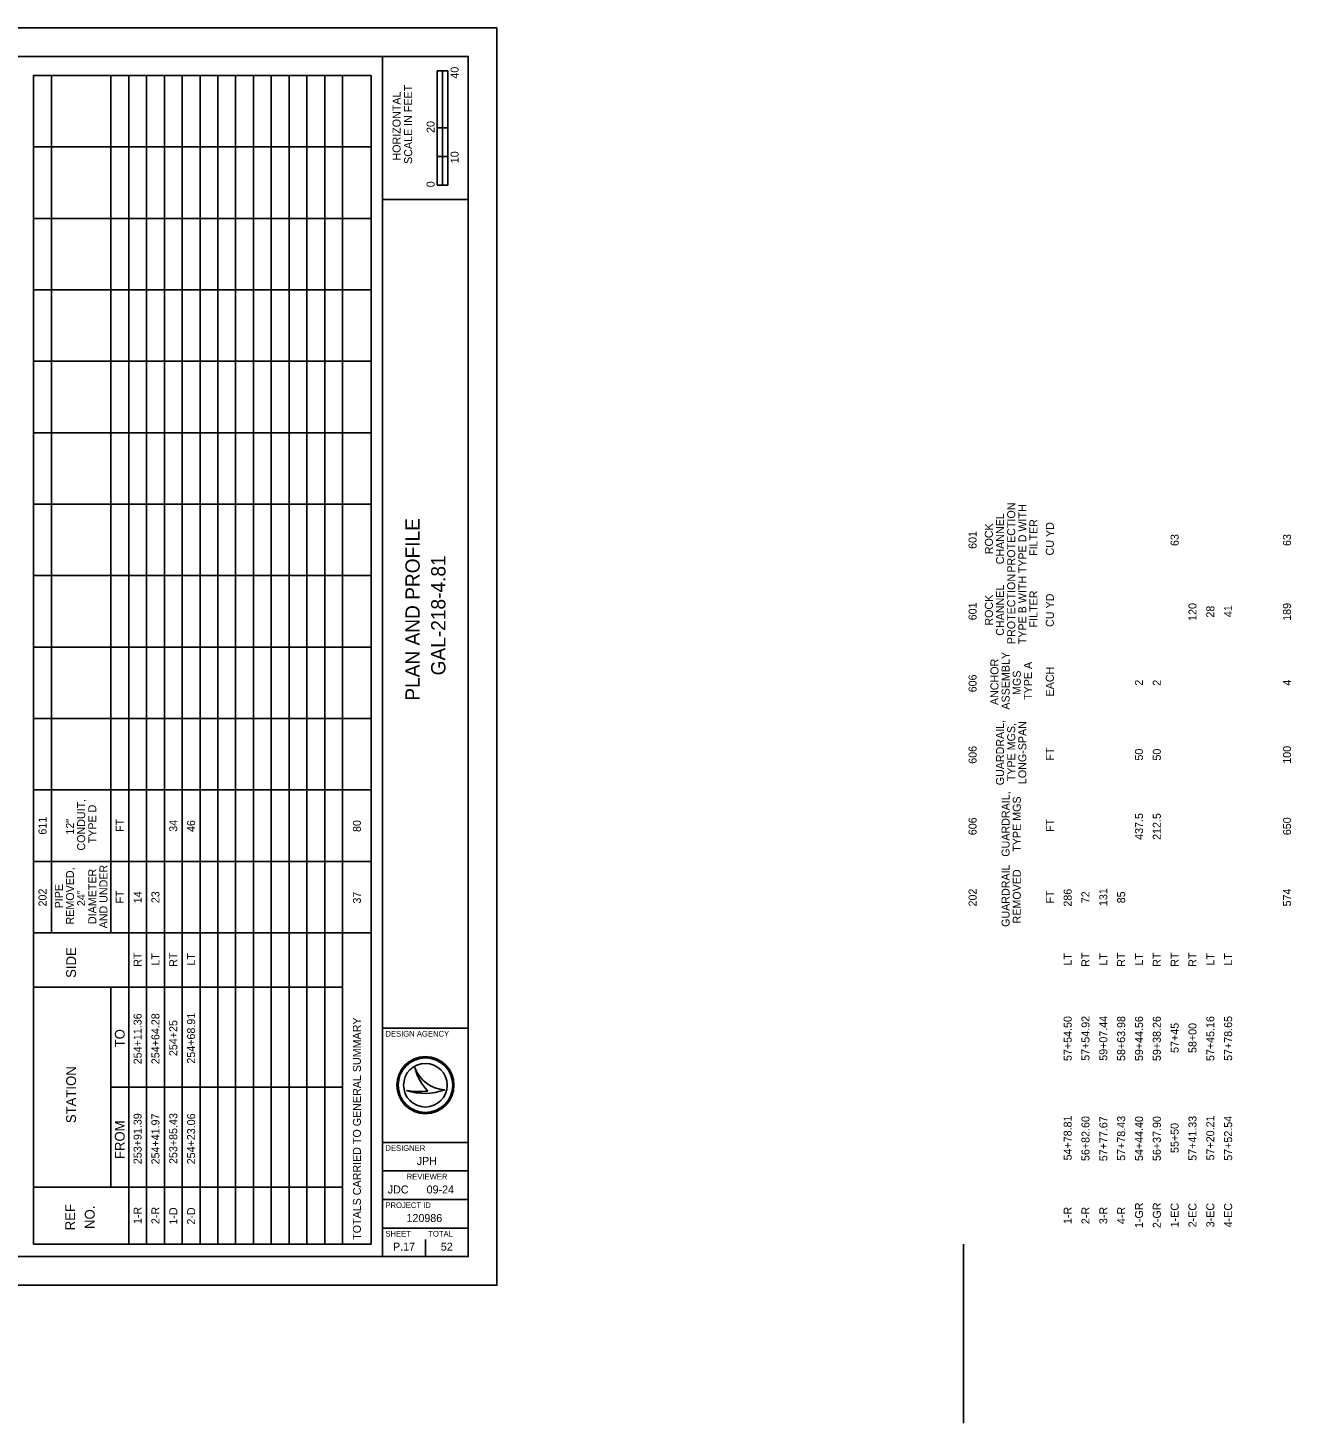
# Model space of a CAD drawing. Extents: x -593 to 958, y -48 to 786.
# Drawn here: x 515.9 to 958, y -48.3 to 440 of the extents above; entities that cross this region are included whole.
import ezdxf

# ---------------------------------------------------------------- set-up
doc = ezdxf.new("R2010")
doc.units = 0
for name, color, linetype in [('DR_X_Culvert', 7, 'Continuous'), ('PF_P_Grade_Line', 7, 'Continuous'), ('PF_X_Ground_Line', 7, 'Continuous'), ('SC_Scratch2', 7, 'Continuous'), ('XS_X_Pavt', 7, 'Continuous')]:
    doc.layers.add(name, color=color, linetype=linetype)

msp = doc.modelspace()

# ---------------------------------------------------------------- linework, layer by layer
at = {"layer": 'DR_X_Culvert'}
for p, q in [((640, 10), (640, 430)), ((640, 380), (670, 380)), ((640, 90), (670, 90)), ((640, 50), (670, 50)), ((640, 40), (670, 40)), ((640, 30), (670, 30)), ((640, 20), (670, 20))]:
    msp.add_line(p, q, dxfattribs=at)
msp.add_lwpolyline([(30, 430), (670, 430), (670, 10), (30, 10)], close=True, dxfattribs=at)
at = {"layer": 'PF_X_Ground_Line'}
msp.add_lwpolyline([(0, 0), (680, 0), (680, 440), (0, 440)], close=True, dxfattribs=at)
at = {"layer": 'SC_Scratch2'}
msp.add_line((843.37, 14.32), (843.37, -48.25), dxfattribs=at)
at = {"layer": 'XS_X_Pavt'}
for p, q in [((659.13, 385), (659.13, 425)), ((662.88, 425), (659.13, 425)), ((659.13, 405), (659.13, 425)), ((659.13, 425), (661, 425)), ((661, 425), (661.02, 425)), ((661.02, 425), (661.02, 405)), ((662.88, 425), (662.88, 385)), ((517.87, 423.33), (517.87, 14.32)), ((636.03, 423.33), (517.87, 423.33)), ((524.11, 423.33), (524.11, 123.33)), ((544.91, 423.33), (544.91, 123.33)), ((551.15, 423.33), (551.15, 14.32)), ((557.39, 423.33), (557.39, 14.32)), ((563.63, 423.33), (563.63, 14.32)), ((569.87, 423.33), (569.87, 14.32)), ((576.11, 423.33), (576.11, 14.32)), ((582.35, 423.33), (582.35, 14.32)), ((588.59, 423.33), (588.59, 14.32)), ((594.83, 423.33), (594.83, 14.32)), ((601.07, 423.33), (601.07, 14.32)), ((607.31, 423.33), (607.31, 14.32)), ((613.55, 423.33), (613.55, 14.32)), ((619.79, 423.33), (619.79, 14.32)), ((626.03, 423.33), (626.03, 14.32)), ((636.03, 423.33), (636.03, 14.32)), ((661.02, 405), (659.13, 405)), ((662.87, 405), (661, 405)), ((661, 405), (661, 395)), ((662.87, 395), (662.87, 405)), ((636.03, 398.33), (517.87, 398.33)), ((661, 395), (659.13, 395)), ((659.13, 395), (659.13, 385)), ((661, 385), (661, 395)), ((661, 395), (662.87, 395)), ((662.88, 385), (659.13, 385)), ((659.13, 385), (661, 385)), ((636.03, 373.33), (517.87, 373.33)), ((636.03, 348.33), (517.87, 348.33)), ((636.03, 323.33), (517.87, 323.33)), ((636.03, 298.33), (517.87, 298.33)), ((636.03, 273.33), (517.87, 273.33)), ((636.03, 248.33), (517.87, 248.33)), ((636.03, 223.33), (517.87, 223.33)), ((636.03, 198.33), (517.87, 198.33)), ((636.03, 173.33), (517.87, 173.33)), ((636.03, 148.33), (517.87, 148.33)), ((636.03, 123.33), (517.87, 123.33)), ((517.87, 104.32), (626.03, 104.32)), ((544.91, 104.32), (544.91, 34.32)), ((651.35, 76.19), (651.35, 76.19)), ((544.91, 69.32), (626.03, 69.32)), ((655, 70), (655, 70)), ((661.75, 68.37), (661.75, 68.37)), ((648.34, 68.19), (648.34, 68.19)), ((517.87, 34.32), (626.03, 34.32)), ((655, 10), (655, 16)), ((517.87, 14.32), (636.03, 14.32)), ((647.5, 13.5), (647.5, 13.5))]:
    msp.add_line(p, q, dxfattribs=at)
for radius in [10, 9.54, 9.54, 7.64]:
    msp.add_circle((655, 70), radius, dxfattribs=at)
for centre, radius, start, end in [((662.32, 79.95), 11.6, 198.9257, 198.9319), ((666.93, 79.4), 15.91, 191.6379, 191.6421), ((662.32, 79.95), 11.6, 198.9319, 267.1657), ((666.93, 79.4), 15.91, 191.6421, 226.0947), ((654.79, 87.4), 20.26, 251.4576, 290.0832), ((652.96, 93.09), 25.32, 259.4964, 259.4995), ((654.79, 87.4), 20.26, 251.4527, 251.4576), ((652.96, 93.09), 25.32, 259.4995, 276.6672)]:
    msp.add_arc(centre, radius, start, end, dxfattribs=at)

# ---------------------------------------------------------------- texts
at = {"layer": 'PF_P_Grade_Line'}
for s, p in [('PROTECTION', (861.41, 249.36)), ('CHANNEL', (857.5, 252.28)), ('TYPE D WITH', (865.31, 249.16)), ('601', (847.89, 257.68)), ('ROCK', (853.6, 255.82)), ('FILTER', (869.21, 255.21)), ('CU YD', (874.93, 255.38)), ('63', (918.61, 258.68)), ('63', (957.93, 258.68)), ('CHANNEL', (857.5, 227.28)), ('PROTECTION', (861.41, 224.36)), ('TYPE B WITH', (865.31, 224.31)), ('ROCK', (853.6, 230.82)), ('FILTER', (869.21, 230.21)), ('CU YD', (874.93, 230.38)), ('601', (847.89, 232.68)), ('120', (924.85, 232.49)), ('28', (931.09, 233.62)), ('41', (937.33, 233.8)), ('189', (957.93, 232.51)), ('ASSEMBLY', (859.45, 201.43)), ('ANCHOR', (855.55, 203.02)), ('MGS', (863.36, 206.56)), ('TYPE A', (867.26, 204.82)), ('EACH', (874.93, 206.04)), ('606', (847.89, 207.48)), ('2', (906.13, 209.79)), ('2', (912.37, 209.79)), ('4', (957.93, 209.8)), ('GUARDRAIL,', (857.5, 174.95)), ('TYPE MGS,', (861.41, 176.36)), ('LONG-SPAN', (865.31, 175.36)), ('606', (847.89, 182.48)), ('FT', (874.93, 183.59)), ('50', (906.13, 183.6)), ('50', (912.37, 183.6)), ('100', (957.93, 182.49)), ('GUARDRAIL,', (859.45, 149.95)), ('CONDUIT,', (535.91, 152.1)), ('TYPE D', (539.81, 154.65)), ('TYPE MGS', (863.36, 151.7)), ('611', (522.39, 157.68)), ('12"', (532.01, 157.68)), ('FT', (549.43, 158.59)), ('34', (568.15, 158.68)), ('46', (574.39, 158.59)), ('80', (632.43, 158.6)), ('606', (847.89, 157.48)), ('FT', (874.93, 158.59)), ('437.5', (906.13, 155.85)), ('212.5', (912.37, 155.85)), ('650', (957.93, 157.49)), ('AND UNDER', (543.72, 124.87)), ('GUARDRAIL', (859.45, 125.39)), ('REMOVED,', (532.01, 126.24)), ('DIAMETER', (539.81, 126.39)), ('REMOVED', (863.36, 126.61)), ('202', (522.39, 132.55)), ('PIPE', (528.11, 131.88)), ('24"', (535.91, 132.68)), ('FT', (549.43, 133.59)), ('14', (555.67, 133.68)), ('23', (561.91, 133.68)), ('37', (632.43, 133.53)), ('202', (847.89, 132.55)), ('FT', (874.93, 133.59)), ('286', (881.17, 132.48)), ('72', (887.41, 133.67)), ('131', (893.65, 132.68)), ('85', (899.89, 133.65)), ('574', (957.93, 132.56)), ('RT', (555.67, 111.45)), ('LT', (561.91, 111.84)), ('RT', (568.15, 111.45)), ('LT', (574.39, 111.84)), ('LT', (881.17, 111.84)), ('RT', (887.41, 111.45)), ('LT', (893.65, 111.84)), ('RT', (899.89, 111.45)), ('LT', (906.13, 111.84)), ('RT', (912.37, 111.45)), ('RT', (918.61, 111.45)), ('RT', (924.85, 111.45)), ('LT', (931.09, 111.84)), ('LT', (937.33, 111.84)), ('254+11.36', (555.67, 77.33)), ('254+64.28', (561.91, 77.36)), ('254+68.91', (574.39, 77.54)), ('57+54.50', (881.17, 78.46)), ('57+54.92', (887.41, 78.53)), ('59+07.44', (893.65, 78.54)), ('58+63.98', (899.89, 78.47)), ('59+44.56', (906.13, 78.45)), ('59+38.26', (912.37, 78.45)), ('57+45.16', (931.09, 78.45)), ('57+78.65', (937.33, 78.5)), ('254+25', (568.15, 80.18)), ('57+45', (918.61, 81.3)), ('58+00', (924.85, 81.25)), ('253+91.39', (555.67, 42.37)), ('254+41.97', (561.91, 42.27)), ('253+85.43', (568.15, 42.42)), ('254+23.06', (574.39, 42.31)), ('54+78.81', (881.17, 43.66)), ('56+82.60', (887.41, 43.46)), ('57+77.67', (893.65, 43.39)), ('57+78.43', (899.89, 43.52)), ('54+44.40', (906.13, 43.46)), ('56+37.90', (912.37, 43.46)), ('57+41.33', (924.85, 43.54)), ('57+20.21', (931.09, 43.66)), ('57+52.54', (937.33, 43.54)), ('55+50', (918.61, 46.25)), ('1-R', (555.67, 21.38)), ('2-R', (561.91, 21.38)), ('1-D', (568.15, 21.21)), ('2-D', (574.39, 21.21)), ('1-R', (881.17, 21.38)), ('2-R', (887.41, 21.38)), ('3-R', (893.65, 21.38)), ('4-R', (899.89, 21.38)), ('1-GR', (906.13, 19.99)), ('2-GR', (912.37, 19.99)), ('1-EC', (918.61, 20.25)), ('2-EC', (924.85, 20.25)), ('3-EC', (931.09, 20.25)), ('4-EC', (937.33, 20.25))]:
    msp.add_text(s, height=2.8, rotation=90, dxfattribs=at).set_placement(p)
at = {"layer": 'XS_X_Pavt'}
for s, height, p in [('40', 2.8, (666.61, 422.25)), ('SCALE IN FEET', 2.8, (650.35, 392.41)), ('HORIZONTAL', 2.8, (646.3, 393.58)), ('20', 2.8, (658.21, 403.25)), ('10', 2.8, (666.61, 392.65)), ('0', 2.8, (658.21, 384.23)), ('PLAN AND PROFILE', 5, (653, 204.55)), ('GAL-218-4.81', 5, (662, 213.41)), ('SIDE', 3.435, (532.71, 107.55)), ('TOTALS CARRIED TO GENERAL SUMMARY', 2.8, (632.43, 15.89)), ('TO', 3.435, (549.75, 83.25)), ('STATION', 3.435, (532.71, 56.71)), ('FROM', 3.435, (549.75, 44.15)), ('REF', 3.436, (532.36, 19.22)), ('NO.', 3.436, (539.23, 19.69))]:
    msp.add_text(s, height=height, rotation=90, dxfattribs=at).set_placement(p)
for s, height, p in [('DESIGN AGENCY', 2, (641, 87)), ('DESIGNER', 2, (641, 47)), ('JPH', 2.8, (651.97, 42.1)), ('JDC', 2.8, (641.82, 32.1)), ('REVIEWER', 2, (648.44, 37)), ('09-24', 2.8, (655.42, 32.1)), ('PROJECT ID', 2, (641, 27)), ('120986', 2.8, (648.38, 22.1)), ('SHEET', 2, (641, 17)), ('P.17', 2.8, (643.67, 12.1)), ('TOTAL', 2, (656, 17)), ('52', 2.8, (660.39, 12.1))]:
    msp.add_text(s, height=height, dxfattribs=at).set_placement(p)

doc.saveas('drawing.dxf')
